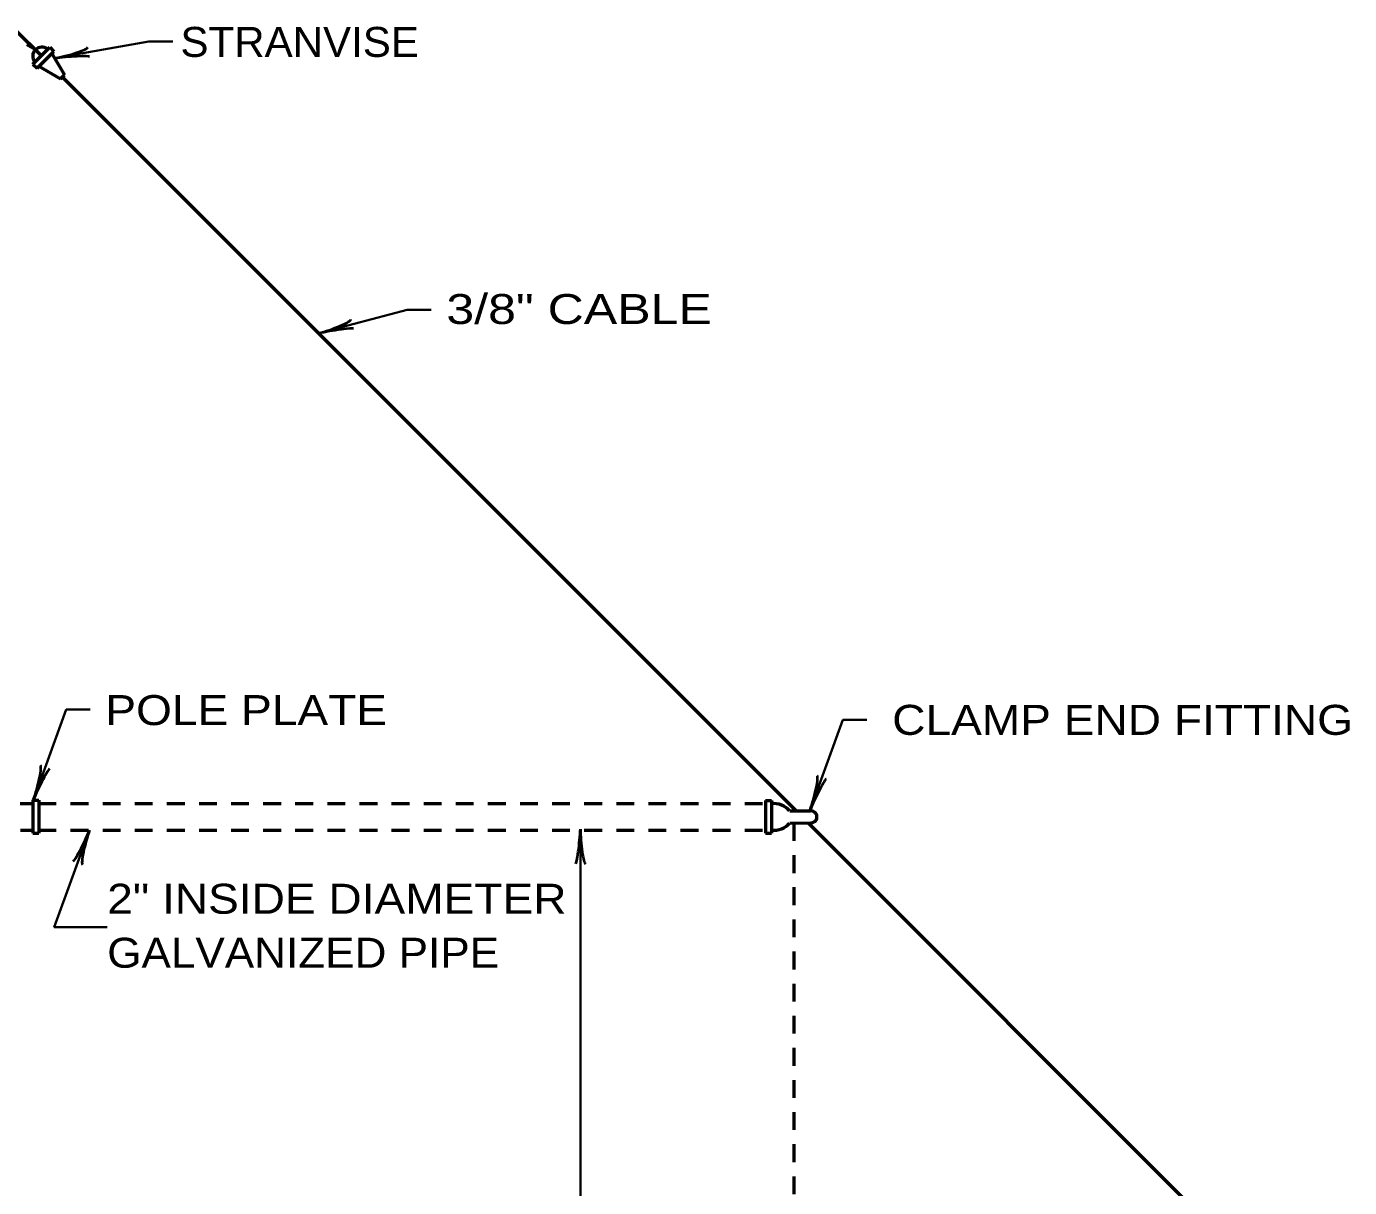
# Model space of a CAD drawing. Extents: x -1 to 679, y 0 to 440.
# Drawn here: x 319.7 to 431, y 104.8 to 202.5 of the extents above; entities that cross this region are included whole.
import ezdxf

# ---------------------------------------------------------------- set-up
doc = ezdxf.new("R2010")
doc.units = 0
doc.linetypes.add('SHORT_DASHED', pattern=[2.7, 1.5, -1.2])
doc.layers.add('1', color=7, linetype='Continuous', lineweight=53)

msp = doc.modelspace()

# ---------------------------------------------------------------- linework, layer by layer
at = {"layer": '1'}
for p, q in [((318.819, 202.135), (320.959, 200.015)), ((320.479, 200.495), (319.759, 200.895)), ((320.259, 199.295), (321.679, 200.715)), ((320.619, 198.935), (322.039, 200.355)), ((321.679, 200.715), (322.039, 200.355)), ((320.259, 199.295), (320.619, 198.935)), ((321.859, 200.175), (322.919, 198.395)), ((320.779, 199.115), (322.579, 198.055)), ((322.579, 198.055), (322.919, 198.395)), ((322.739, 198.215), (384.399, 136.555)), ((319.199, 137.135), (320.259, 137.135)), ((320.259, 137.395), (320.259, 134.615)), ((320.259, 137.395), (320.759, 137.395)), ((320.759, 137.395), (320.759, 134.615)), ((381.879, 137.375), (381.879, 134.615)), ((381.879, 137.375), (382.379, 137.375)), ((382.379, 137.375), (382.379, 134.615)), ((383.919, 136.495), (385.659, 136.495)), ((319.239, 134.875), (320.259, 134.875)), ((383.919, 135.475), (385.739, 135.495)), ((385.459, 135.495), (430.039, 90.935)), ((320.259, 134.615), (320.759, 134.615)), ((381.879, 134.615), (382.379, 134.615))]:
    msp.add_line(p, q, dxfattribs=at)
at = {"layer": '1', "linetype": 'SHORT_DASHED'}
for p, q in [((320.739, 137.135), (381.879, 137.135)), ((320.739, 134.875), (381.879, 134.875)), ((384.279, 135.475), (384.279, 78.775))]:
    msp.add_line(p, q, dxfattribs=at)
at = {"layer": '1', "lineweight": 35}
for points in [[(322.099, 199.775), (330.019, 201.175), (332.039, 201.175)], [(344.319, 176.655), (351.739, 178.635), (353.759, 178.635)], [(320.319, 137.435), (323.079, 145.015), (325.079, 145.015)], [(385.639, 136.595), (388.399, 144.155), (390.419, 144.155)], [(325.019, 134.875), (322.059, 126.735), (326.519, 126.735)], [(366.319, 134.955), (366.319, 68.675), (366.319, 50.235)]]:
    msp.add_lwpolyline(points, dxfattribs=at)
at = {"layer": '1'}
for centre, radius, start, end in [((321.015, 199.957), 0.759, 50.20411, 219.79589), ((382.605, 135.409), 1.702, 39.94521, 97.50756), ((385.702, 135.994), 0.505, 265.53287, 94.46714), ((382.605, 136.576), 1.702, 262.49244, 320.05479)]:
    msp.add_arc(centre, radius, start, end, dxfattribs=at)
at = {"layer": '1', "lineweight": 40}
for centre, major_axis, ratio, start_param, end_param in [((323.136, 200.243), (-1.745, -0.468), 0.122415, 0.8963533, 3.1415927), ((323.25, 199.764), (1.774, 0.133), 0.07063, 6.2823074, 8.5597026), ((345.311, 177.205), (-1.698, -0.618), 0.122415, 0.8963533, 3.1415927), ((345.311, 177.205), (-1.698, -0.618), 0.122415, 0.8963533, 3.1415927), ((345.467, 176.738), (1.756, 0.287), 0.07063, 6.2823074, 8.5597026), ((345.467, 176.738), (1.756, 0.287), 0.07063, 6.2823074, 8.5597026), ((320.43, 138.567), (-0.468, -1.745), 0.122415, 0.8963533, 3.1415927), ((320.902, 138.427), (-0.772, -1.603), 0.07063, 3.1407148, 5.41811), ((385.752, 137.715), (-0.468, -1.745), 0.122415, 0.8963533, 3.1415927), ((386.224, 137.574), (-0.772, -1.603), 0.07063, 3.1407148, 5.41811), ((324.437, 133.883), (-0.772, -1.603), 0.07063, 6.2823074, 8.5597026), ((324.91, 133.742), (0.468, 1.745), 0.122415, 0.8963533, 3.1415927), ((366.102, 133.827), (-0.177, -1.77), 0.07063, 6.2823074, 8.5597026), ((366.594, 133.857), (-0.157, 1.8), 0.122415, 0.8963533, 3.1415927)]:
    msp.add_ellipse(centre, major_axis=major_axis, ratio=ratio, start_param=start_param, end_param=end_param, dxfattribs=at)

# ---------------------------------------------------------------- texts
at = {"layer": '1'}
for s, width, p in [('STRANVISE', 1.05, (332.679, 199.895)), ('3/8" CABLE', 1.25, (355.039, 177.435)), ('POLE PLATE', 1.15, (326.359, 143.715)), ('CLAMP END FITTING', 1.15, (392.539, 142.895)), ('2" INSIDE DIAMETER', 1.15, (326.519, 127.855)), ('GALVANIZED PIPE', 1.1, (326.519, 123.315))]:
    msp.add_text(s, height=2.52, dxfattribs=dict(at, width=width)).set_placement(p)

doc.saveas('drawing.dxf')
